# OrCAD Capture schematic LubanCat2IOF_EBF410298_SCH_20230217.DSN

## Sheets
1 10 USB HUB: size A4; title: 野火_EBF RK3568 底板; rev: V1.0; note: USB HUB; note: https://yehuosm.tmall.com
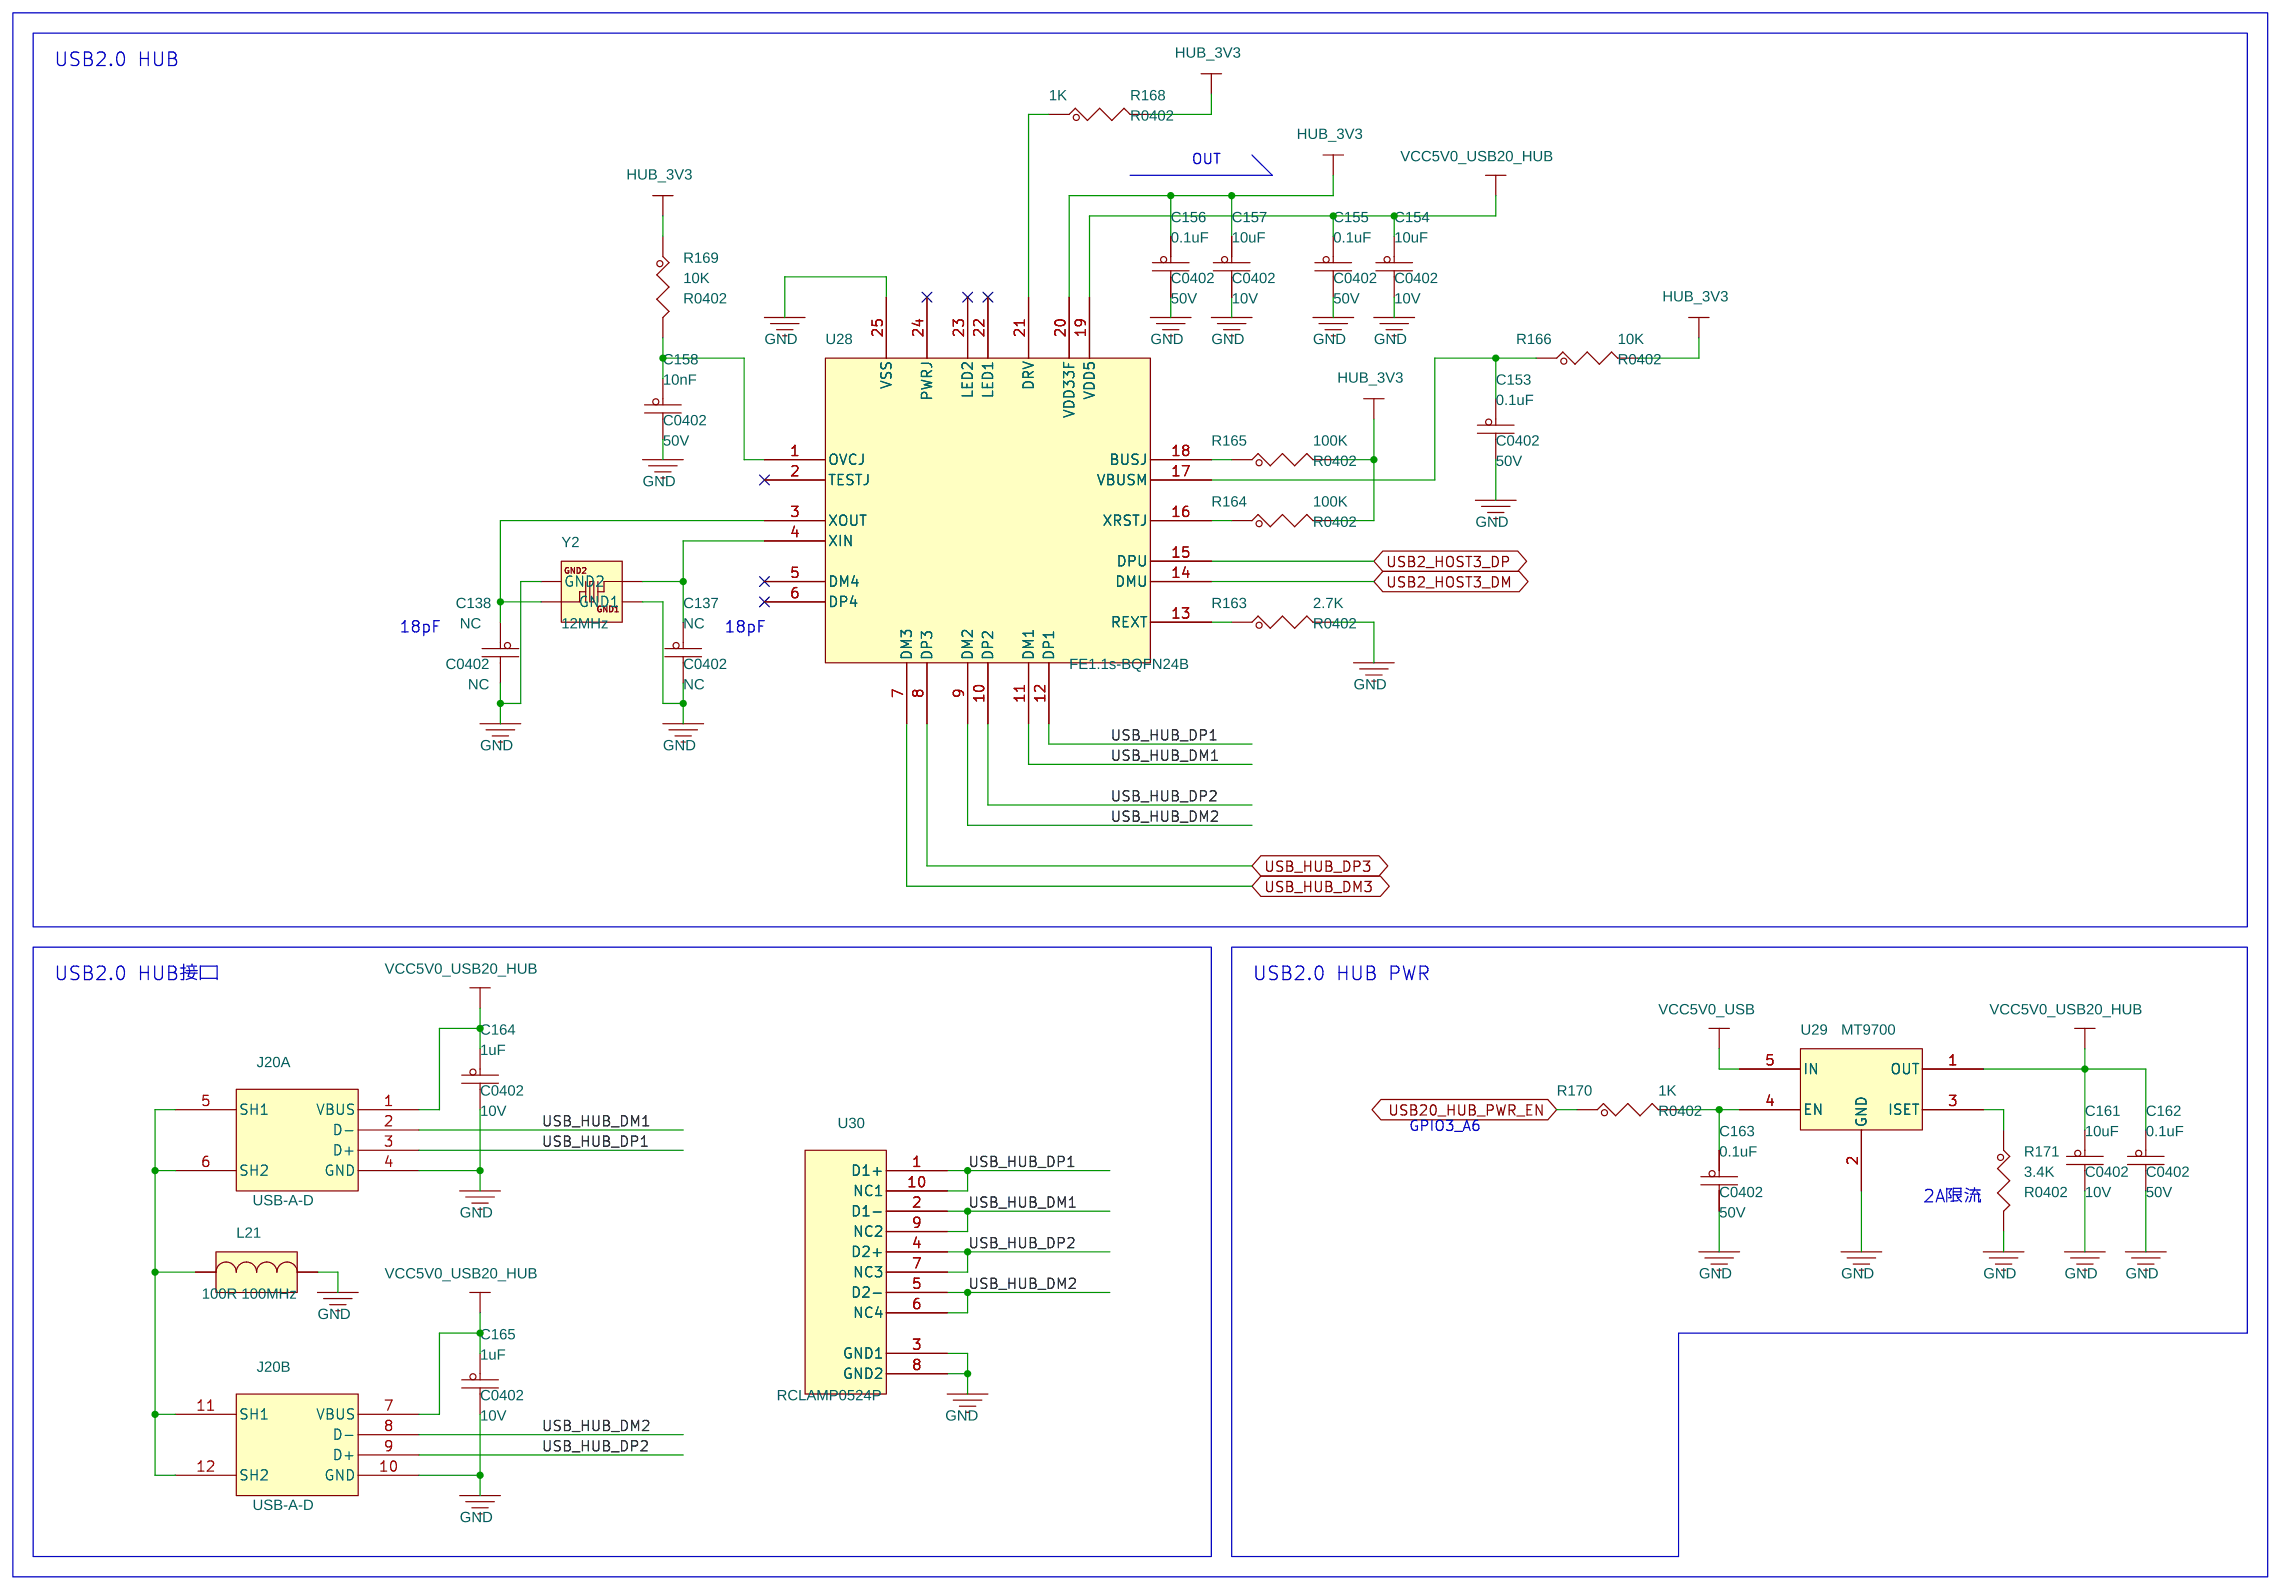
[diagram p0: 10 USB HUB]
2 13 MIPI DSI: size A4; note: MIPI DSI
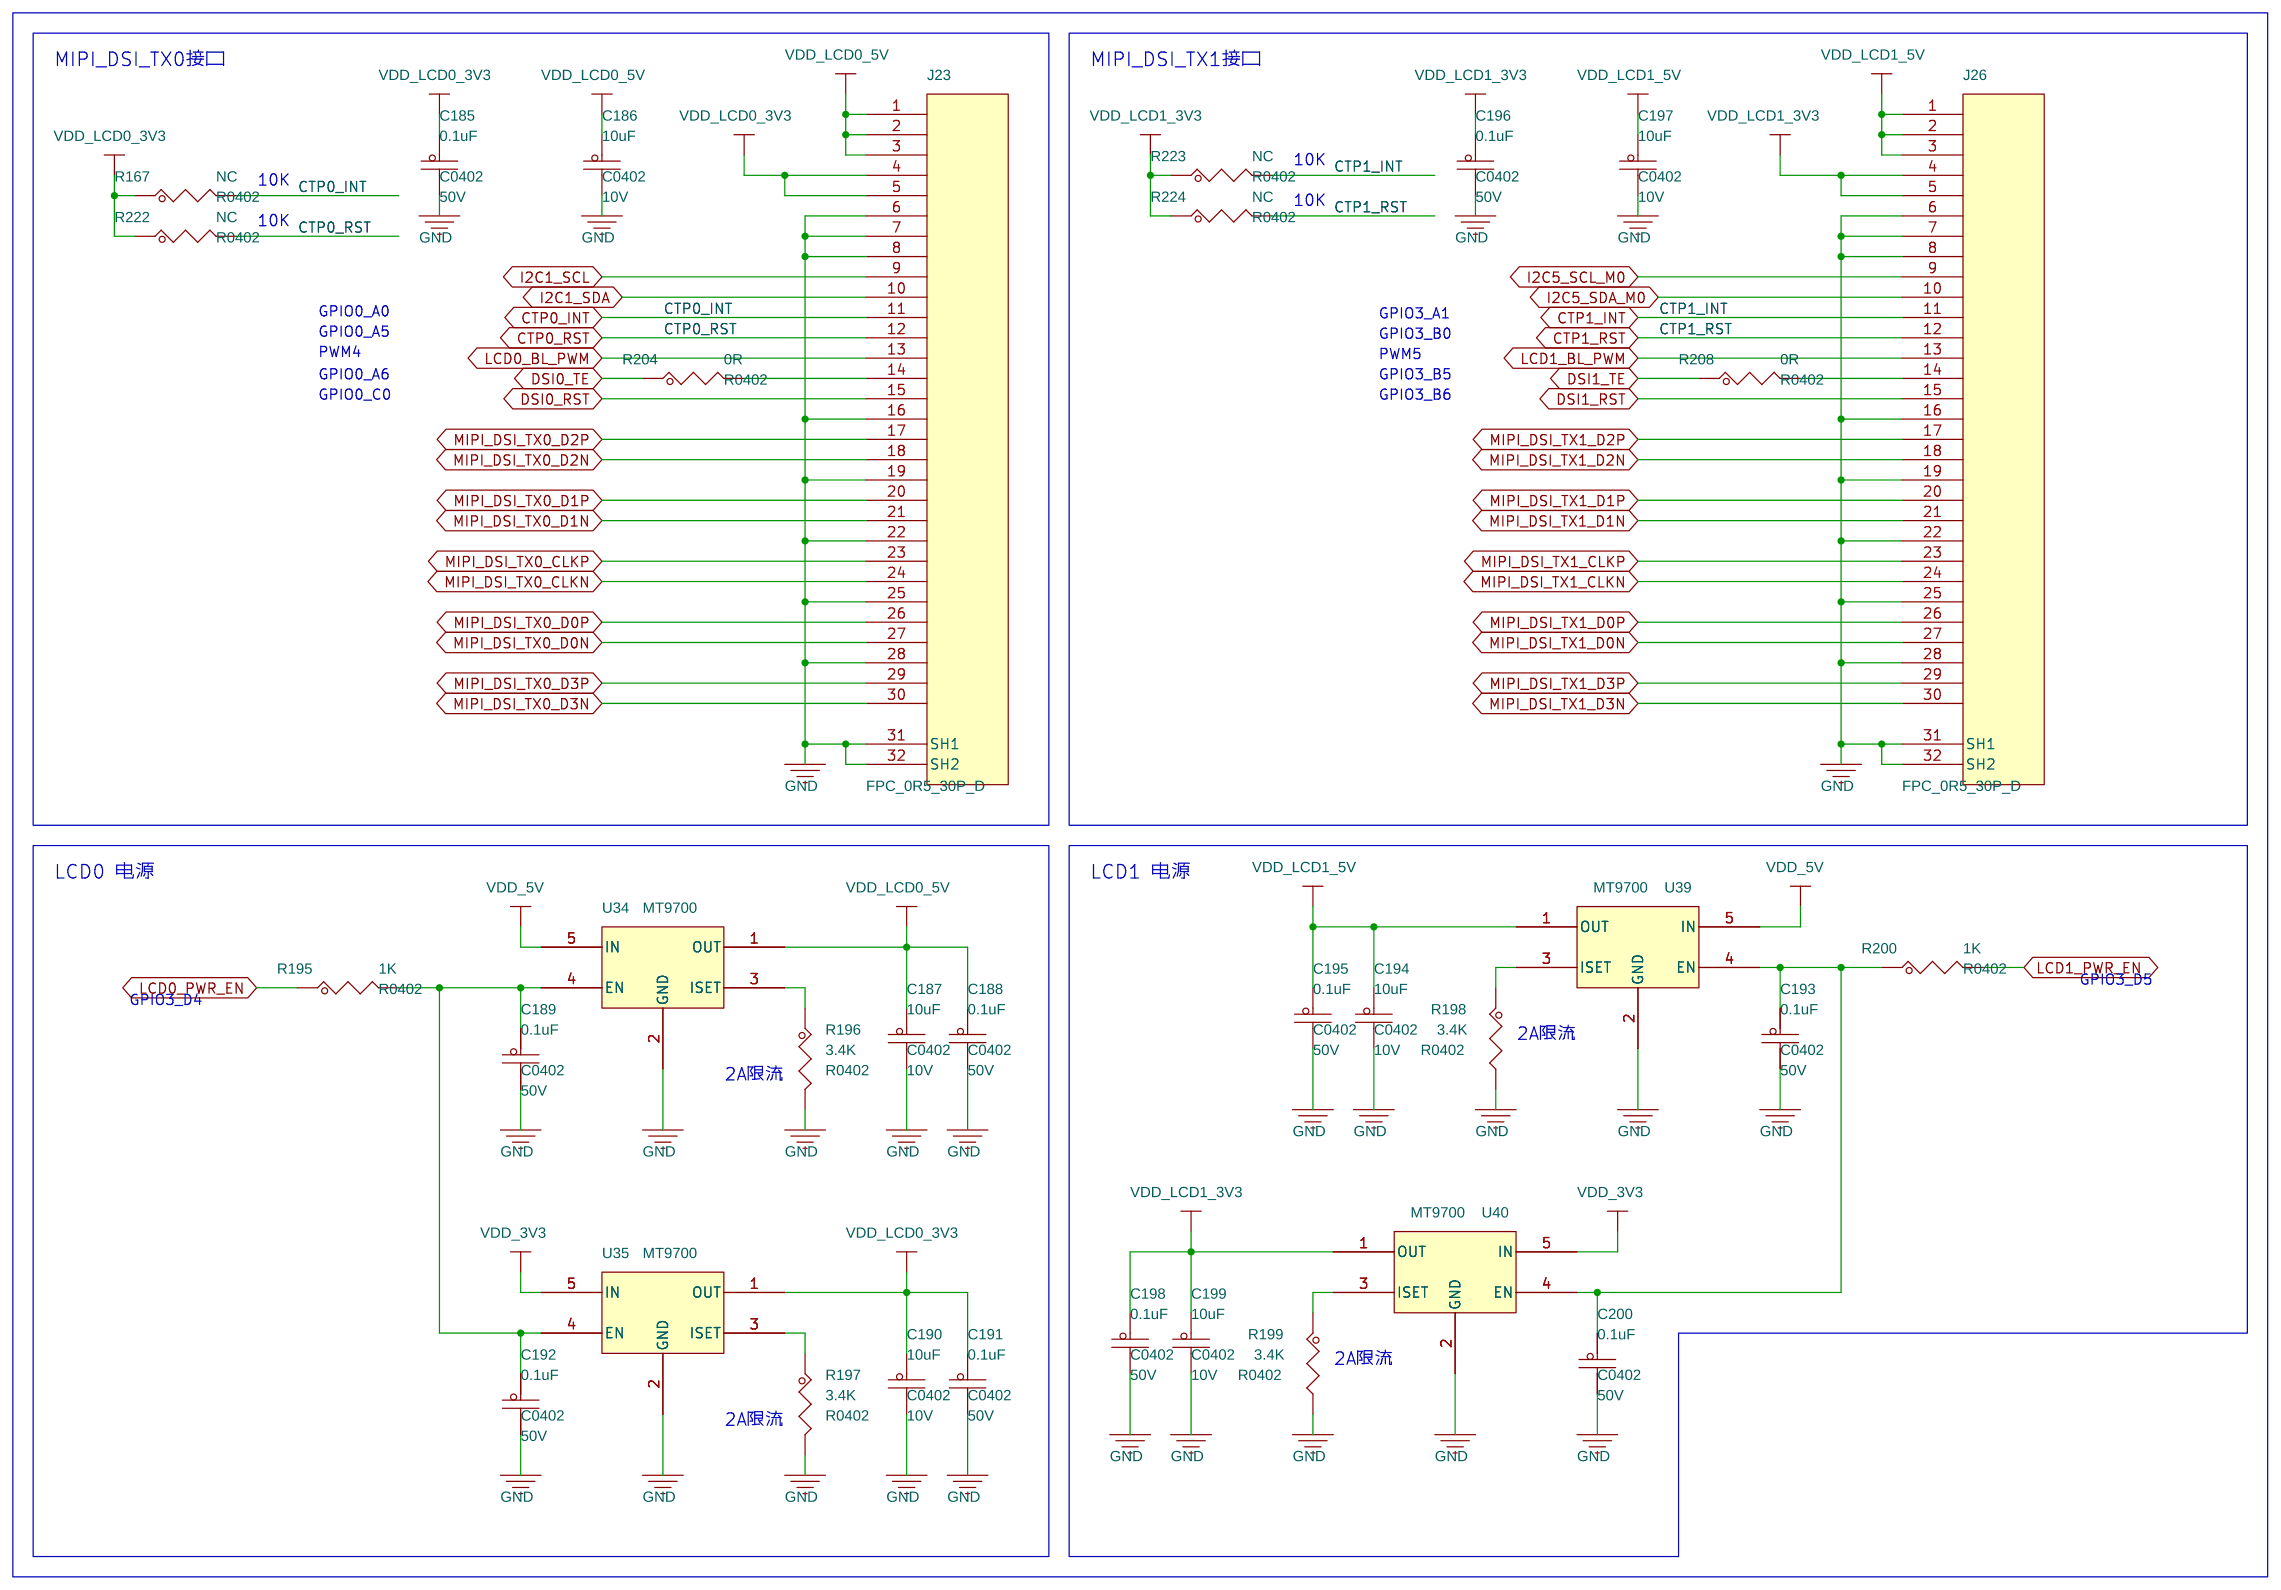
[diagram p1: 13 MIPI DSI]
3 06 DEBUG/RS485/RS232: size A4; note: DEBUG/RS485/RS232
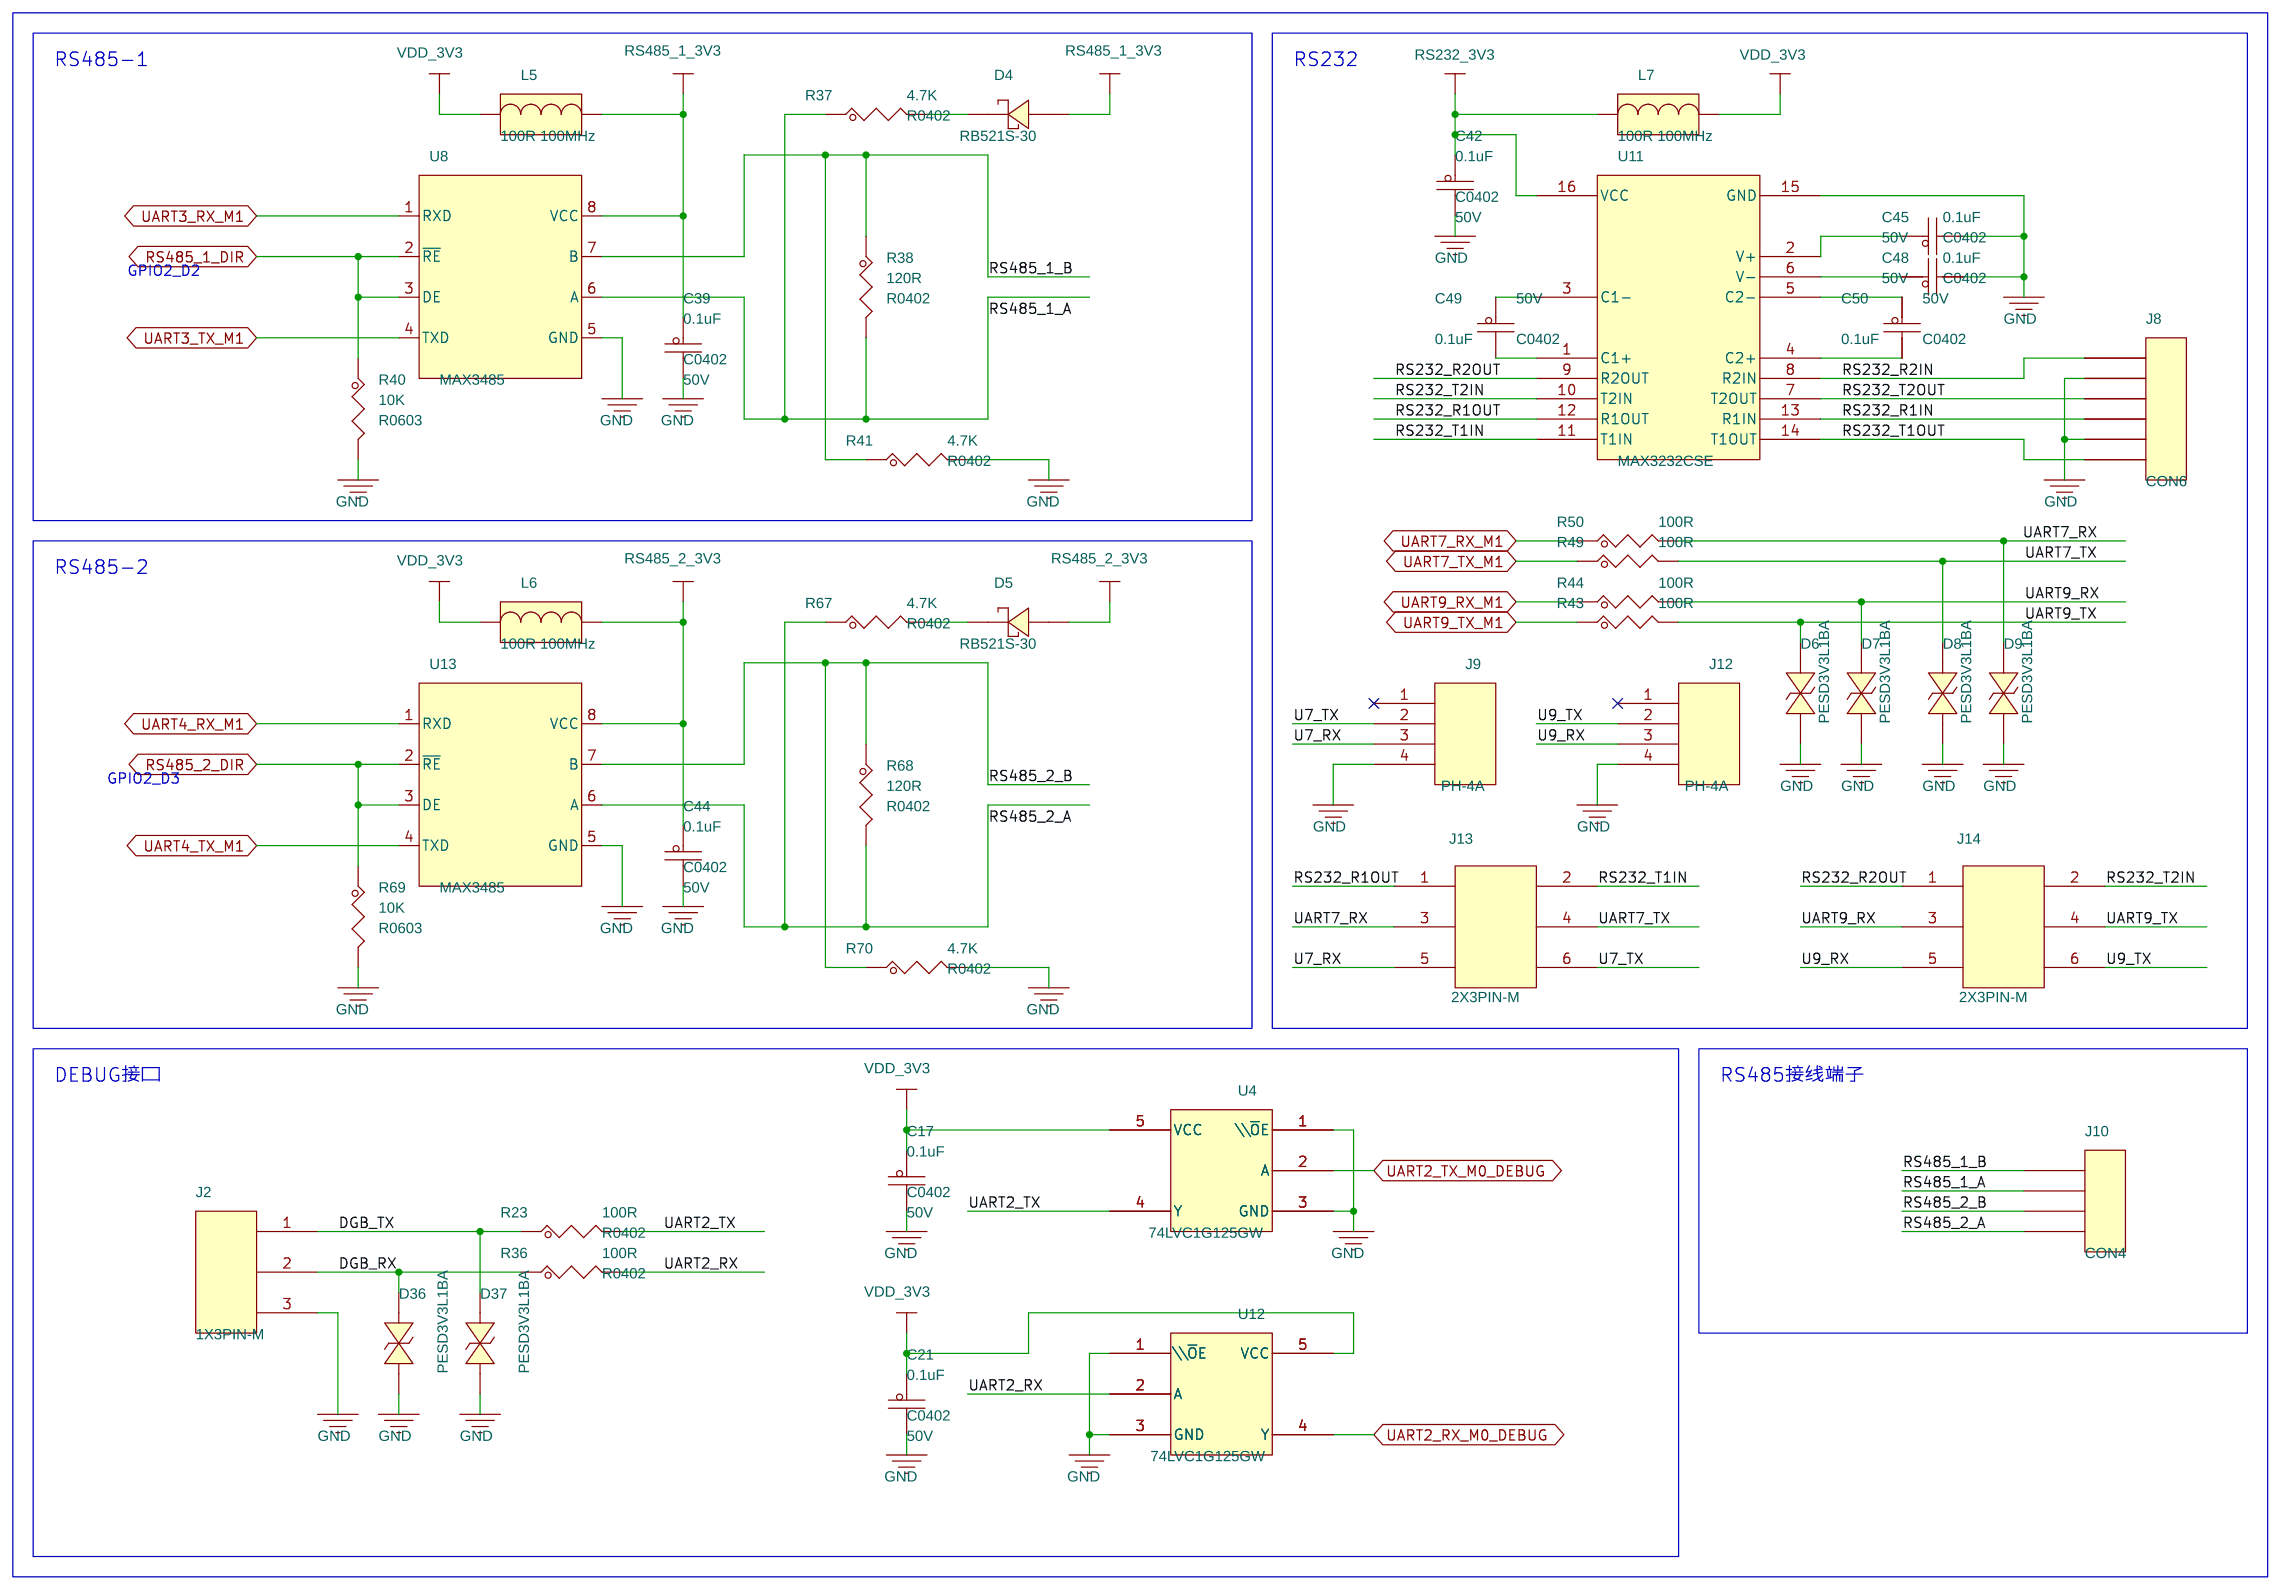
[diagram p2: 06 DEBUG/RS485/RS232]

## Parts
sheet 06 DEBUG/RS485/RS232
C17  0.1uF  [C0402]
C21  0.1uF  [C0402]
C39  0.1uF  [C0402]
C42  0.1uF  [C0402]
C44  0.1uF  [C0402]
C45  0.1uF  [C0402]
C48  0.1uF  [C0402]
C49  0.1uF  [C0402]
C50  0.1uF  [C0402]
D4  RB521S-30  [SOD523]
D5  RB521S-30  [SOD523]
D6  PESD3V3L1BA  [sod323_t]
D7  PESD3V3L1BA  [sod323_t]
D8  PESD3V3L1BA  [sod323_t]
D9  PESD3V3L1BA  [sod323_t]
D36  PESD3V3L1BA  [sod323_t]
D37  PESD3V3L1BA  [sod323_t]
J2  1X3PIN-M  [DIP_3p_2p54]
J8  CON6  [DB2ERC-3P81-6P]
J9  PH-4A  [PH-1X4-2P0]
J10  CON4  [DB2ERC-3P81-4P]
J12  PH-4A  [PH-1X4-2P0]
J13  2X3PIN-M  [DIP-2X3-2P54]
J14  2X3PIN-M  [DIP-2X3-2P54]
L5  100R 100MHz  [L0603]
L6  100R 100MHz  [L0603]
L7  100R 100MHz  [L0603]
R23  100R  [R0402]
R36  100R  [R0402]
R37  4.7K  [R0402]
R38  120R  [R0402]
R40  10K  [R0603]
R41  4.7K  [R0402]
R43  100R  [R0402]
R44  100R  [R0402]
R49  100R  [R0402]
R50  100R  [R0402]
R67  4.7K  [R0402]
R68  120R  [R0402]
R69  10K  [R0603]
R70  4.7K  [R0402]
U4  74LVC1G125GW  [SOT-353]
U8  MAX3485  [SOP8]
U11  MAX3232CSE  [SOIC16]
U12  74LVC1G125GW  [SOT-353]
U13  MAX3485  [SOP8]
sheet 10 USB HUB
C137  NC  [C0402]
C138  NC  [C0402]
C153  0.1uF  [C0402]
C154  10uF  [C0402]
C155  0.1uF  [C0402]
C156  0.1uF  [C0402]
C157  10uF  [C0402]
C158  10nF  [C0402]
C161  10uF  [C0402]
C162  0.1uF  [C0402]
C163  0.1uF  [C0402]
C164  1uF  [C0402]
C165  1uF  [C0402]
J20  USB-A-D  [USB-A-D]  (sections A,B)
L21  100R 100MHz  [L0603]
R163  2.7K  [R0402]
R164  100K  [R0402]
R165  100K  [R0402]
R166  10K  [R0402]
R168  1K  [R0402]
R169  10K  [R0402]
R170  1K  [R0402]
R171  3.4K  [R0402]
U28  FE1.1s-BQFN24B  [QFN24]
U29  MT9700  [SOT23-5]
U30  RCLAMP0524P  [USON_10]
Y2  12MHz  [3225]
sheet 13 MIPI DSI
C185  0.1uF  [C0402]
C186  10uF  [C0402]
C187  10uF  [C0402]
C188  0.1uF  [C0402]
C189  0.1uF  [C0402]
C190  10uF  [C0402]
C191  0.1uF  [C0402]
C192  0.1uF  [C0402]
C193  0.1uF  [C0402]
C194  10uF  [C0402]
C195  0.1uF  [C0402]
C196  0.1uF  [C0402]
C197  10uF  [C0402]
C198  0.1uF  [C0402]
C199  10uF  [C0402]
C200  0.1uF  [C0402]
J23  FPC_0R5_30P_D  [FPC-30P-0P5]
J26  FPC_0R5_30P_D  [FPC-30P-0P5]
R167  NC  [R0402]
R195  1K  [R0402]
R196  3.4K  [R0402]
R197  3.4K  [R0402]
R198  3.4K  [R0402]
R199  3.4K  [R0402]
R200  1K  [R0402]
R204  0R  [R0402]
R208  0R  [R0402]
R222  NC  [R0402]
R223  NC  [R0402]
R224  NC  [R0402]
U34  MT9700  [SOT23-5]
U35  MT9700  [SOT23-5]
U39  MT9700  [SOT23-5]
U40  MT9700  [SOT23-5]

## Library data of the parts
C17 C21 C39 C42 C44 C45 C48-C50 C153 C155 C156 C162 C163 C185 C188 C189 C191-C193 C195 C196 C198 C200 = CAP_NP: Voltage: 50V; 规格: 贴片电容0.1uF 10% 50V X5R 0402; 规格编号: 0402X104K500NT; 规格书: 风华电容.pdf; 价格: 0.029826; 类别: 贴片电容0402; 品牌: 风华; 生命周期: 量产; 条码: EBF29060118
D4 D5 = DIODE_SCHTKY: 规格: 直流反向耐压(Vr)：30V 平均整流电流(Io)：200mA 正向压降(Vf)：500mV@200mA 30V@100mA,VF=350mV@10mA; 规格书: 江苏长电_RB521S-30.pdf; 价格: 0.06781; 类别: 贴片肖特基二极管; 品牌: 江苏长电; 生命周期: 量产; 条码: EBFCIS221114153437
D6-D9 D36 D37 = DIODE_BI-DIR_TRIG: 规格: 防静电保护ESD二极管 箝位电压26V 击穿电压5.8V 反向关断电压3.3V; 规格编号: PESD3V3L1BA 115; 规格书: 安世-PESD3V3L1BA-115.pdf; 价格: 0.31497; 类别: 贴片ESD; 品牌: 安世; 生命周期: 量产; 丝印: AB; 条码: EBF29140003
J2 = 1X3PIN: 规格: 排针 总PIN数3 间距2.54mm 直插; 规格书: 州日_单排针_直插_2P54.pdf; 类别: 直插单排排针; 生命周期: 量产; 条码: EBF29020039
J8 = CON6: 规格: 绿色插拔式接线端子 间距3.81mm 90度弯针 6PIN; 规格编号: WJ15EDGRC-3.81-6P; 规格书: 康奈克斯电气-绿色端子弯针插座.pdf; 价格: 0.301748; 类别: 绿色插拔式接线端子; 品牌: 康奈克斯电气; 生命周期: 量产; 条码: EBF29040013
J9 J12 = 1X4PIN: 规格: 直针PH2.0-4P 间距2.0MM 拔插式 接插件; 规格书: 博穆精密-PH2.0.pdf; 价格: 0.017; 可替代料: EBF29020025; 类别: PH连接器; 品牌: 博穆精密; 生命周期: 量产; 条码: EBF29020025
J10 = CON4: 规格: 插拔式接线端子 间距3.81mm 90度弯针 4PIN; 规格编号: WJ15EDGRC-3.81-4P; 规格书: 康奈克斯电气-绿色端子弯针插座.pdf; 价格: 0.198381; 类别: 绿色插拔式接线端子; 品牌: 康奈克斯电气; 生命周期: 量产; 条码: EBF29040009
J13 J14 = 2X3PIN: 规格: 排针 总PIN数6 间距2.54mm 直插; 规格书: 州日_双排针_直插_2P54.pdf; 类别: 直插双排排针; 生命周期: 量产; 条码: EBF29020030
L5-L7 L21 = BEAD: 规格: 磁珠100Ω @100MHz 额定电流3A 直流电阻30mΩ; 规格编号: UPZ1608E101-3R0TF; 规格书: 顺络-磁珠.pdf; 价格: 0.021567; 类别: 贴片磁珠0603; 品牌: 顺络; 生命周期: 量产; 条码: EBF29050038
R23 R36 R43 R44 R49 R50 = RES: 规格: 贴片电阻100R 1% 1/16W 0402; 规格编号: RI0402L1000FT; 规格书: 合科泰-RI系列电阻.pdf; 类别: 贴片电阻0402; 品牌: 合科泰; 生命周期: 量产; 条码: EBF29070053
R37 R41 R67 R70 = RES: 规格: 贴片电阻4.7K 1% 1/16W 0402; 规格编号: RI0402L4701FT; 规格书: 合科泰-RI系列电阻.pdf; 类别: 贴片电阻0402; 品牌: 合科泰; 生命周期: 量产; 条码: EBF29070047
R38 R68 = RES: 规格: 贴片电阻120R 1% 1/16W 0402; 规格编号: 0402WGF1200TCE; 规格书: 厚声-无铅厚膜电阻.pdf; 价格: 0.002198; 类别: 贴片电阻0402; 品牌: 厚声; 生命周期: 量产; 条码: EBF29070275
R40 R69 = RES: 规格: 贴片电阻10K 1% 1/10W 0603; 规格编号: RI0603L1002FT; 规格书: 合科泰-RI系列电阻.pdf; 类别: 贴片电阻0603; 品牌: 合科泰; 生命周期: 量产; 条码: EBF29070074
U4 U12 = 74LVC1G125: 规格: 时钟缓冲器 驱动器 具有三态输出 允许工作电压为3.3V 5.5V 典型工作电流100mA; 规格书: 74LVC1G125GW.pdf; 价格: 0.182409; 类别: 隔离器件; 品牌: 安世; 生命周期: 量产; 丝印: VM; 条码: EBF29170001
U8 U13 = TJA1057GT3: 规格: RS-485/RS-422芯片 收发器 允许32个器件连接总线 协议类别RS-485 电源电压3.3V 数据速率10Mbps; 规格编号: MAX3485ED; 规格书: HTC_MAX3485ED.pdf; 价格: 1.31; 类别: RS485/RS422芯片; 品牌: HTC; 生命周期: 量产; 条码: EBF29150034
U11 = MAX3232CSE: 规格: RS232芯片 收发器 驱动器/接收器数：2/2 协议类别RS232 电源电压3V~5.5V 数据速率235kbps; 规格编号: MAX3232CSE+T; 规格书: MAX3232CSE.pdf; 价格: 7.73; 类别: RS232芯片; 品牌: 美信; 生命周期: 量产; 丝印: MAX3232; 条码: EBF29150006
C137 C138 = CAP_NP: 规格: 贴片电容NC 预留; 类别: 贴片电容0402; 条码: EBF29060149
C154 C157 C161 C186 C187 C190 C194 C197 C199 = CAP_NP: Voltage: 10V; 规格: 贴片电容10uF 20% 10V X5R 0402; 规格编号: CL05A106MP8NUB8; 规格书: 三星电容.pdf; 价格: 0.518415; 类别: 贴片电容0402; 品牌: 三星; 生命周期: 量产; 条码: EBF29060247
C158 = CAP_NP: Voltage: 50V; 规格: 贴片电容10nF 10% 50V X7R 0402; 规格编号: CC0402KRX7R9BB103; 规格书: 国巨-贴片电容.pdf; 价格: 0.003808; 类别: 贴片电容0402; 品牌: 国巨; 生命周期: 量产; 条码: EBF29060245
C164 C165 = CAP_NP: Voltage: 10V; 规格: 贴片电容1uF 10% 10V X5R 0402; 规格编号: 0402X105K100NT; 规格书: 风华电容.pdf; 价格: 0.01191; 类别: 贴片电容0402; 品牌: 风华; 生命周期: 量产; 条码: EBF29060121
J20 = USB-A-D: 规格: 双层USB接口 A型接口 90度双排弯插脚 AF母座 焊接式; 规格编号: 907-111A1012D10200; 规格书: 精拓金-双层USB.pdf; 价格: 0.22; 类别: USB接口; 品牌: 精拓金; 生命周期: 量产; 条码: EBF29020027
R163 = RES: 规格: 贴片电阻2.7K 1% 1/16W 0402; 规格编号: RMC04022.7K1%N; 规格书: 幸亚电阻.pdf; 价格: 0.016497; 类别: 贴片电阻0402; 品牌: 幸亚; 生命周期: 量产; 条码: EBF29070202
R164 R165 = RES: 规格: 贴片电阻100K 1% 1/16W 0402; 规格编号: RI0402L1003FT; 规格书: 合科泰-RI系列电阻.pdf; 类别: 贴片电阻0402; 品牌: 合科泰; 生命周期: 量产; 条码: EBF29070054
R166 R169 = RES: 规格: 贴片电阻10K 1% 1/16W 0402; 规格编号: 0402WGF1002TCE; 规格书: 厚声-无铅厚膜电阻.pdf; 价格: 0.002773; 类别: 贴片电阻0402; 品牌: 厚声; 生命周期: 量产; 条码: EBF29070046
R168 R170 R195 R200 = RES: 规格: 贴片电阻1K 1% 1/16W 0402; 规格编号: RI0402L1001FT; 规格书: 合科泰-RI系列电阻.pdf; 类别: 贴片电阻0402; 品牌: 合科泰; 生命周期: 量产; 条码: EBF29070050
R171 R196-R199 = RES: 规格: 贴片电阻3.4K 1% 1/16W 0402; 规格编号: RI0402L3401FT; 规格书: 合科泰-RI系列电阻.pdf; 类别: 贴片电阻0402; 品牌: 合科泰; 生命周期: 量产; 条码: EBF29070186
U28 = FE1.1s-BQFN24B: 规格: USB HUB芯片 工作电压3.3V 5V 协议类别USB2.0 支持高速(480Mbps) 全速(12Mbps)和低速(1.5Mbps)模式; 规格书: FE1.1s-BQFN24B.pdf; 类别: USB芯片; 品牌: 汤铭科技; 生命周期: 量产; 条码: EBF29150035
U29 U34 U35 U39 U40 = MT9700: 规格: 负载开关 工作电压2.4V-5.5V 最大电流2A 过流保护; 规格书: MT9700.pdf; 价格: 0.483492; 类别: 功率开关; 品牌: 西安航天民芯; 生命周期: 量产; 丝印: D00HA-X; 条码: EBF29280004
U30 = RCLAMP0524P: 规格: TVS二极管 箝位电压17V 击穿电压8V 反向关断电压5V; 规格书: 台舟-RCLAMP0524P.pdf; 价格: 0.185957; 类别: 贴片TVS; 品牌: 台舟; 生命周期: 量产; 条码: EBF29140046
Y2 = CRYSTAL_4P: 规格: 无源晶振12MHZ 80Ω 20pF 3225; 规格编号: X322512MSB4SI; 规格书: 扬兴科技-贴片晶振.pdf; 价格: 0.327763; 可替代料: EBF29100013; 类别: 贴片晶振 3225; 品牌: 扬兴科技; 生命周期: 量产; 条码: EBF29100013
J23 J26 = FPC-30P: 规格: FPC连接器 针脚数30 间距0.5mm 高度2.0mm 下接 卧贴 翻盖式; 规格编号: FPC-05F-30PH20; 规格书: FPC-05F-NPH20.pdf; 类别: FPC连接器; 品牌: 讯普; 生命周期: 量产; 条码: EBF29040079
R167 R222-R224 = RES: 规格: 贴片电阻NC 预留; 类别: 贴片电阻0402; 条码: EBF29070087
R204 R208 = RES: 规格: 贴片电阻0R 1% 1/16W 0402; 规格编号: RI0402L000FT; 规格书: 合科泰-RI系列电阻.pdf; 类别: 贴片电阻0402; 品牌: 合科泰; 生命周期: 量产; 条码: EBF29070049

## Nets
GND: C17.2 C21.2 C39.2 C42.2 C44.2 C45.2 C48.2 C137.2 C138.2 C153.2 C154.2 C155.2 C156.2 C157.2 C158.2 C161.2 C162.2 C163.2 C164.2 C165.2 C185.2 C186.2 C187.2 C188.2 C189.2 C190.2 C191.2 C192.2 C193.2 C194.2 C195.2 C196.2 C197.2 C198.2 C199.2 C200.2 D6.2 D7.2 D8.2 D9.2 D36.2 D37.2 J2.3 J8.2 J8.5 J9.4 J12.4 J20.4(GND) J20.10(GND) J23.6 J23.7 J23.8 J23.16 J23.19 J23.22 J23.25 J23.28 J23.31(SH1) J23.32(SH2) J26.6 J26.7 J26.8 J26.16 J26.19 J26.22 J26.25 J26.28 J26.31(SH1) J26.32(SH2) L21.2 R40.2 R41.2 R69.2 R70.2 R163.2 R171.2 R196.2 R197.2 R198.2 R199.2 U4.1(\\~{O}E) U4.3(GND) U8.5(GND) U11.15(GND) U12.1(\\~{O}E) U12.3(GND) U13.5(GND) U28.25(VSS) U29.2(GND) U30.3(GND1) U30.8(GND2) U34.2(GND) U35.2(GND) U39.2(GND) U40.2(GND) Y2.2(GND1) Y2.4(GND2)
VCC5V0_USB: U29.5(IN)
VCC5V0_USB20_HUB: C154.1 C155.1 C161.1 C162.1 C164.1 C165.1 J20.1(VBUS) J20.7(VBUS) U28.19(VDD5) U29.1(OUT)
VDD_3V3: C17.1 C21.1 L5.1 L6.1 L7.2 U4.5(VCC) U12.5(VCC) U35.5(IN) U40.5(IN)
VDD_5V: U34.5(IN) U39.5(IN)
VDD_LCD0_3V3: C185.1 C190.1 C191.1 J23.4 J23.5 R167.1 R222.1 U35.1(OUT)
VDD_LCD0_5V: C186.1 C187.1 C188.1 J23.1 J23.2 J23.3 U34.1(OUT)
VDD_LCD1_3V3: C196.1 C198.1 C199.1 J26.4 J26.5 R223.1 R224.1 U40.1(OUT)
VDD_LCD1_5V: C194.1 C195.1 C197.1 J26.1 J26.2 J26.3 U39.1(OUT)
CTP0_INT: J23.11 R167.2
CTP0_RST: J23.12 R222.2
CTP1_INT: J26.11 R223.2
CTP1_RST: J26.12 R224.2
DGB_RX: D36.1 J2.2 R36.1
DGB_TX: D37.1 J2.1 R23.1
DSI0_RST: J23.15
DSI0_TE: R204.1
DSI1_RST: J26.15
DSI1_TE: R208.1
HUB_3V3: C156.1 C157.1 R164.2 R165.2 R166.2 R168.2 R169.1 U28.20(VDD33F)
I2C1_SCL: J23.9
I2C1_SDA: J23.10
I2C5_SCL_M0: J26.9
I2C5_SDA_M0: J26.10
LCD0_BL_PWM: J23.13
LCD0_PWR_EN: R195.1
LCD1_BL_PWM: J26.13
LCD1_PWR_EN: R200.2
MIPI_DSI_TX0_CLKN: J23.24
MIPI_DSI_TX0_CLKP: J23.23
MIPI_DSI_TX0_D0N: J23.27
MIPI_DSI_TX0_D0P: J23.26
MIPI_DSI_TX0_D1N: J23.21
MIPI_DSI_TX0_D1P: J23.20
MIPI_DSI_TX0_D2N: J23.18
MIPI_DSI_TX0_D2P: J23.17
MIPI_DSI_TX0_D3N: J23.30
MIPI_DSI_TX0_D3P: J23.29
MIPI_DSI_TX1_CLKN: J26.24
MIPI_DSI_TX1_CLKP: J26.23
MIPI_DSI_TX1_D0N: J26.27
MIPI_DSI_TX1_D0P: J26.26
MIPI_DSI_TX1_D1N: J26.21
MIPI_DSI_TX1_D1P: J26.20
MIPI_DSI_TX1_D2N: J26.18
MIPI_DSI_TX1_D2P: J26.17
MIPI_DSI_TX1_D3N: J26.30
MIPI_DSI_TX1_D3P: J26.29
RS232_3V3: C42.1 L7.1 U11.16(VCC)
RS232_R1IN: J8.4 U11.13(R1IN)
RS232_R1OUT: J13.1 U11.12(R1OUT)
RS232_R2IN: J8.1 U11.8(R2IN)
RS232_R2OUT: J14.1 U11.9(R2OUT)
RS232_T1IN: J13.2 U11.11(T1IN)
RS232_T1OUT: J8.6 U11.14(T1OUT)
RS232_T2IN: J14.2 U11.10(T2IN)
RS232_T2OUT: J8.3 U11.7(T2OUT)
RS485_1_3V3: C39.1 D4.1 L5.2 U8.8(VCC)
RS485_1_A: J10.2 R37.1 R38.2 U8.6(A)
RS485_1_B: J10.1 R38.1 R41.1 U8.7(B)
RS485_1_DIR: R40.1 U8.2(~{RE}) U8.3(DE)
RS485_2_3V3: C44.1 D5.1 L6.2 U13.8(VCC)
RS485_2_A: J10.4 R67.1 R68.2 U13.6(A)
RS485_2_B: J10.3 R68.1 R70.1 U13.7(B)
RS485_2_DIR: R69.1 U13.2(~{RE}) U13.3(DE)
U7_RX: J9.3 J13.5
U7_TX: J9.2 J13.6
U9_RX: J12.3 J14.5
U9_TX: J12.2 J14.6
UART2_RX: R36.2 U12.2(A)
UART2_RX_M0_DEBUG: U12.4(Y)
UART2_TX: R23.2 U4.4(Y)
UART2_TX_M0_DEBUG: U4.2(A)
UART3_RX_M1: U8.1(RXD)
UART3_TX_M1: U8.4(TXD)
UART4_RX_M1: U13.1(RXD)
UART4_TX_M1: U13.4(TXD)
UART7_RX: D9.1 J13.3 R50.2
UART7_RX_M1: R50.1
UART7_TX: D8.1 J13.4 R49.2
UART7_TX_M1: R49.1
UART9_RX: D7.1 J14.3 R44.2
UART9_RX_M1: R44.1
UART9_TX: D6.1 J14.4 R43.2
UART9_TX_M1: R43.1
USB2_HOST3_DM: U28.14(DMU)
USB2_HOST3_DP: U28.15(DPU)
USB20_HUB_PWR_EN: R170.1
USB_HUB_DM1: J20.2(D-) U28.11(DM1) U30.2(D1-) U30.9(NC2)
USB_HUB_DM2: J20.8(D-) U28.9(DM2) U30.5(D2-) U30.6(NC4)
USB_HUB_DM3: U28.7(DM3)
USB_HUB_DP1: J20.3(D+) U28.12(DP1) U30.1(D1+) U30.10(NC1)
USB_HUB_DP2: J20.9(D+) U28.10(DP2) U30.4(D2+) U30.7(NC3)
USB_HUB_DP3: U28.8(DP3)
N15772454: J26.14 R208.2
N15774097: J23.14 R204.2
N17438974: D4.2 R37.2
N17440531: D5.2 R67.2
N17441588: C49.1 U11.3(C1-)
N17441590: C49.2 U11.1(C1+)
N17441592: C50.1 U11.5(C2-)
N17441594: C50.2 U11.4(C2+)
N17441596: C48.1 U11.6(V-)
N17441598: C45.1 U11.2(V+)
N17505436: R163.1 U28.13(REXT)
N17505526: R164.1 U28.16(XRSTJ)
N17505593: R165.1 U28.18(BUSJ)
N17505596: C153.1 R166.1 U28.17(VBUSM)
N17506485: R168.1 U28.21(DRV)
N17506866: C158.1 R169.2 U28.1(OVCJ)
N17515649: C138.1 U28.3(XOUT) Y2.1
N17515683: C137.1 U28.4(XIN) Y2.3
N17516865: J20.5(SH1) J20.6(SH2) J20.11(SH1) J20.12(SH2) L21.1
N17517489: C163.1 R170.2 U29.4(EN)
N17517506: R171.1 U29.3(ISET)
N17562506: C189.1 C192.1 R195.2 U34.4(EN) U35.4(EN)
N17562520: R196.1 U34.3(ISET)
N17562633: R197.1 U35.3(ISET)
N17563970: C193.1 C200.1 R200.1 U39.4(EN) U40.4(EN)
N17564290: R198.1 U39.3(ISET)
N17565184: R199.1 U40.3(ISET)

Not connected (* = marked no-connect by the designer): J9 1*; J12 1*; U28 2(TESTJ)* 5(DM4)* 6(DP4)* 22(LED1)* 23(LED2)* 24(PWRJ)*

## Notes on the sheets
sheet 1
- USB2.0 HUB
- OUT
- 18pF
- 18pF
- USB2.0 HUB接口
- USB2.0 HUB PWR
- GPIO3_A6
- 2A限流
sheet 2
- MIPI_DSI_TX0接口
- MIPI_DSI_TX1接口
- 10K
- 10K
- 10K
- 10K
- GPIO0_A0
- GPIO3_A1
- GPIO0_A5
- GPIO3_B0
- PWM4
- PWM5
- GPIO0_A6
- GPIO3_B5
- GPIO0_C0
- GPIO3_B6
- LCD0 电源
- LCD1 电源
- GPIO3_D5
- GPIO3_D4
- 2A限流
- 2A限流
- 2A限流
- 2A限流
sheet 3
- RS485-1
- RS232
- GPIO2_D2
- RS485-2
- GPIO2_D3
- DEBUG接口
- RS485接线端子
